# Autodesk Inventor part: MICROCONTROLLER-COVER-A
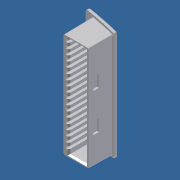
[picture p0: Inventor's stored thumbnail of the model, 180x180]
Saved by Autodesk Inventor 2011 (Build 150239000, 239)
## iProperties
Created: 2008-01
Part Number: MICROCONTROLLER-COVER-A
Document SubType Name: Modeling
Density: 1 g/cm^3
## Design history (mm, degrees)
feature "Base1"
body "Solid1"
